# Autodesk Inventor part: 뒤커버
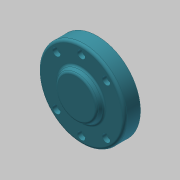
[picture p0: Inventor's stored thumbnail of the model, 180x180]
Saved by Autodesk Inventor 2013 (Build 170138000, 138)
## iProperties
Company: 한국ATC센터
Created: 2015-12
Part Number: 뒤커버
Document SubType Name: Modeling
Designer: mdu
Density: 2.71 g/cm^3
Mass: 104.822 g
Surface Area: 117.742 cm^2
Volume: 38.6798 cm^3
Material: 알루미늄 6061
Author: mdu
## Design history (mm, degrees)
sketch "스케치1"
  geometry: L1 (-10.5, 0)-(10.5, 0); L2 (10.5, 0)-(10.5, 22.5); L3 (10.5, 22.5)-(5.5, 22.5); L4 (5.5, 22.5)-(5.5, 32.5); L5 (5.5, 32.5)-(-6.5, 32.5); L6 (-6.5, 32.5)-(-6.5, 17.5); L7 (-6.5, 17.5)-(-10.5, 15.191); L8 (-10.5, 15.191)-(-10.5, 0); 2 further points
  constraints: 16 end point, 3 parallel, 3 perpendicular, 1 coincident, 1 horizontal, 1 midpoint
  dimensions: "d0" = 21 distance of L1.start L1.end; "d1" = 65 diameter of L5 L1; "d2" = 45 diameter of L3 L1; "d3" = 35 diameter of L6.end L1; "d4" = 120 deg angle of L7 L6; "d5" = 12 distance of L4.end L5.end; "d6" = 5 distance of L2.end L3.end
revolve "회전1" sketch "스케치1" stored, may be unused: angle "d7" = 90 deg
sketch "스케치2"
  geometry: L1 (0, 0)-(32.5, 0); L2 (0, 0)-(0, 26.5); 1 further point
  constraints: 4 end point, 1 horizontal, 1 horizontal alignment, 1 other
  dimensions: "d8" = 90 deg angle of L1 L2; "d9" = 26.5 distance of L1.start L2.end
hole "구멍1" sketch "스케치2" at (0, 26.5) diameter "d10" = 3.4; stored, may be unused: countersink angle "d14" = 90 deg, drill point angle "d16" = 118 deg; dims "d11" = 6, "d12" = 6, "d13" = 3.3, "d15" = 8
fillet "모깎기1" dims "d20" = 2
hole "구멍2" diameter "d23" = 15; stored, may be unused: countersink angle "d27" = 90 deg, drill point angle "d29" = 0 deg; dims "d21" = 10, "d22" = 10, "d24" = 6, "d25" = 35, "d26" = 11, "d28" = 14
chamfer "모따기1" distance "d39" = 1; stored, may be unused: second distance "d40" = 2, angle "d41" = 45 deg
fillet "모깎기2" dims "d42" = 0.3
chamfer "모따기3" distance "d57" = 1; stored, may be unused: second distance "d58" = 2, angle "d59" = 45 deg
fillet "모깎기4" dims "d60" = 1
node "솔리드1"
pattern_circular "원형 패턴1" dims angle "d18" = 360 deg
